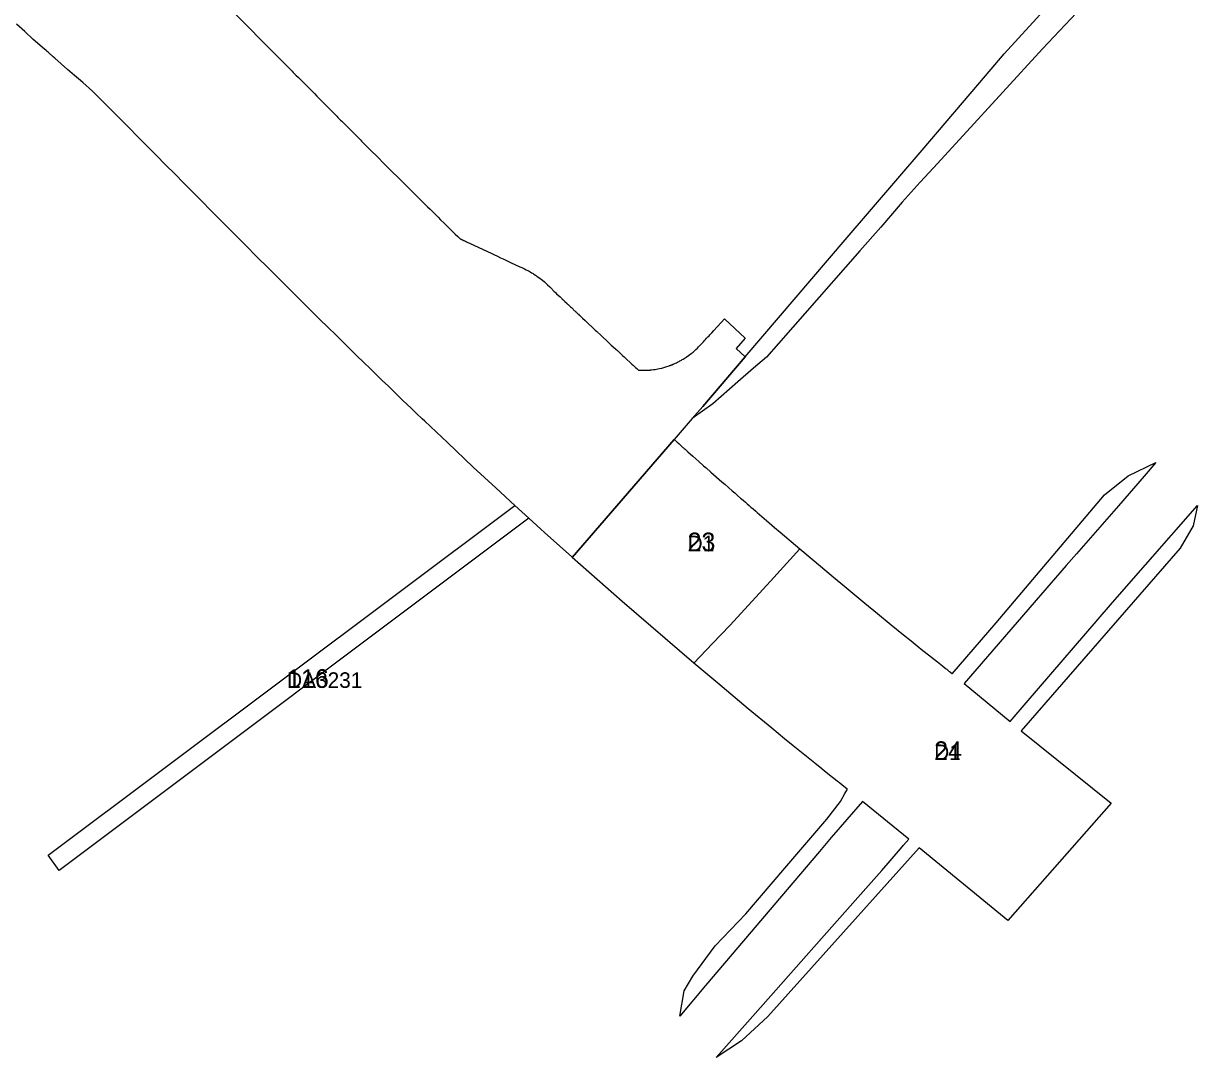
# Model space of a CAD drawing. Extents: x -537012 to -534603, y -1176562 to -1172739.
# Drawn here: x -536079.8 to -535702.9, y -1174980.3 to -1174648.3 of the extents above; entities that cross this region are included whole.
import ezdxf

# ---------------------------------------------------------------- set-up
doc = ezdxf.new("R2010")
doc.units = 0
for name, color, linetype in [('96120023', 7, 'Continuous'), ('96140023', 7, 'Continuous'), ('ID_VPO', 7, 'Continuous'), ('ID_VPS', 7, 'Continuous')]:
    doc.layers.add(name, color=color, linetype=linetype)

msp = doc.modelspace()

# ---------------------------------------------------------------- linework, layer by layer
at = {"layer": '96120023'}
for points in [[(-536047.23, -1174609.35), (-535999.47, -1174657.57), (-535998.21, -1174658.84), (-535997.36, -1174659.7), (-535996.1, -1174660.98), (-535995.25, -1174661.83), (-535994.83, -1174662.25), (-535994.41, -1174662.68), (-535993.56, -1174663.53), (-535993.14, -1174663.96), (-535992.72, -1174664.38), (-535992.3, -1174664.81), (-535991.46, -1174665.66), (-535990.61, -1174666.51), (-535989.77, -1174667.36), (-535988.92, -1174668.21), (-535988.08, -1174669.06), (-535987.24, -1174669.91), (-535986.39, -1174670.77), (-535985.55, -1174671.62), (-535984.71, -1174672.47), (-535983.86, -1174673.32), (-535983.02, -1174674.17), (-535982.6, -1174674.59), (-535982.18, -1174675.01), (-535981.75, -1174675.44), (-535981.33, -1174675.86), (-535980.91, -1174676.29), (-535980.49, -1174676.71), (-535980.07, -1174677.14), (-535979.65, -1174677.56), (-535979.22, -1174677.99), (-535978.8, -1174678.41), (-535978.38, -1174678.83), (-535977.96, -1174679.26), (-535977.54, -1174679.68), (-535977.12, -1174680.11), (-535976.69, -1174680.53), (-535976.27, -1174680.95), (-535975.85, -1174681.38), (-535975.43, -1174681.8), (-535975.01, -1174682.23), (-535974.59, -1174682.65), (-535974.16, -1174683.07), (-535973.74, -1174683.5), (-535973.32, -1174683.92), (-535972.9, -1174684.34), (-535972.48, -1174684.77), (-535972.05, -1174685.19), (-535971.63, -1174685.61), (-535971.21, -1174686.04), (-535970.79, -1174686.46), (-535970.37, -1174686.88), (-535969.95, -1174687.31), (-535968.26, -1174689), (-535966.15, -1174691.11), (-535964.04, -1174693.22), (-535962.35, -1174694.91), (-535961.08, -1174696.17), (-535959.81, -1174697.43), (-535958.54, -1174698.7), (-535957.7, -1174699.54), (-535956.85, -1174700.38), (-535956.43, -1174700.8), (-535955.58, -1174701.64), (-535954.74, -1174702.48), (-535953.89, -1174703.32), (-535953.05, -1174704.16), (-535951.78, -1174705.42), (-535950.93, -1174706.25), (-535950.08, -1174707.09), (-535949.24, -1174707.93), (-535947.97, -1174709.19), (-535946.69, -1174710.44), (-535945.85, -1174711.28), (-535944.57, -1174712.53), (-535943.73, -1174713.36), (-535942.88, -1174714.2), (-535942.03, -1174715.03), (-535941.18, -1174715.87), (-535940.33, -1174716.7), (-535939.63, -1174717.38), (-535939.46, -1174717.47), (-535939.4, -1174717.49), (-535939.36, -1174717.51), (-535939.34, -1174717.52), (-535939.3, -1174717.54), (-535939.26, -1174717.56), (-535939.23, -1174717.57), (-535939.21, -1174717.58), (-535939.19, -1174717.59), (-535939.13, -1174717.62), (-535939.08, -1174717.64), (-535939.04, -1174717.66), (-535939.02, -1174717.67), (-535938.98, -1174717.69), (-535938.96, -1174717.7), (-535938.94, -1174717.71), (-535938.9, -1174717.73), (-535938.87, -1174717.74), (-535938.86, -1174717.75), (-535938.84, -1174717.75), (-535938.83, -1174717.76), (-535938.82, -1174717.76), (-535938.82, -1174717.77), (-535938.81, -1174717.77), (-535938.8, -1174717.77), (-535938.79, -1174717.78), (-535938.78, -1174717.78), (-535938.77, -1174717.79), (-535938.76, -1174717.79), (-535938.75, -1174717.8), (-535938.73, -1174717.81), (-535938.72, -1174717.81), (-535938.71, -1174717.82), (-535938.69, -1174717.82), (-535938.68, -1174717.83), (-535938.66, -1174717.84), (-535938.65, -1174717.84), (-535938.64, -1174717.85), (-535938.62, -1174717.86), (-535938.6, -1174717.87), (-535938.55, -1174717.89), (-535938.54, -1174717.9), (-535938.52, -1174717.9), (-535938.51, -1174717.91), (-535938.5, -1174717.91), (-535938.44, -1174717.94), (-535938.41, -1174717.96), (-535938.37, -1174717.98), (-535938.22, -1174718.04), (-535938.15, -1174718.08), (-535937.86, -1174718.21), (-535937.55, -1174718.36), (-535937.31, -1174718.47), (-535936.55, -1174718.83), (-535933.61, -1174720.2), (-535929.65, -1174722.06), (-535928.75, -1174722.48), (-535927.61, -1174723.01), (-535926.64, -1174723.47), (-535926.16, -1174723.69), (-535925.76, -1174723.88), (-535924.52, -1174724.47), (-535923.38, -1174725), (-535920.41, -1174726.38), (-535919.82, -1174726.66), (-535918.98, -1174727.06), (-535918.39, -1174727.35), (-535917.84, -1174727.62), (-535917.44, -1174727.85), (-535917.08, -1174728.04), (-535916.65, -1174728.29), (-535916.39, -1174728.44), (-535916.15, -1174728.59), (-535915.89, -1174728.76), (-535915.44, -1174729.05), (-535915.14, -1174729.25), (-535914.82, -1174729.47), (-535914.32, -1174729.83), (-535913.2, -1174730.67), (-535912.57, -1174731.22), (-535912.23, -1174731.52), (-535911.54, -1174732.14), (-535910.84, -1174732.83), (-535910.5, -1174733.2), (-535910.11, -1174733.61), (-535909.9, -1174733.82), (-535909.47, -1174734.22), (-535909.04, -1174734.63), (-535908.62, -1174735.04), (-535907.53, -1174736.06), (-535907.07, -1174736.51), (-535906.92, -1174736.65), (-535906.87, -1174736.69), (-535906.82, -1174736.74), (-535906.79, -1174736.77), (-535906.77, -1174736.79), (-535906.75, -1174736.81), (-535906.73, -1174736.82), (-535906.72, -1174736.83), (-535906.71, -1174736.84), (-535906.7, -1174736.85), (-535906.7, -1174736.86), (-535906.69, -1174736.86), (-535906.69, -1174736.87), (-535906.68, -1174736.87), (-535906.68, -1174736.88), (-535906.67, -1174736.88), (-535906.67, -1174736.89), (-535906.66, -1174736.89), (-535906.65, -1174736.9), (-535906.65, -1174736.91), (-535906.64, -1174736.91), (-535906.63, -1174736.92), (-535906.63, -1174736.93), (-535906.62, -1174736.93), (-535906.61, -1174736.94), (-535906.6, -1174736.95), (-535906.42, -1174737.13), (-535906.29, -1174737.24), (-535906.1, -1174737.42), (-535905.96, -1174737.56), (-535905.29, -1174738.19), (-535905.1, -1174738.37), (-535904.94, -1174738.52), (-535904.85, -1174738.61), (-535904.72, -1174738.73), (-535904.63, -1174738.82), (-535904.33, -1174739.1), (-535904.15, -1174739.27), (-535903.9, -1174739.5), (-535903.35, -1174740.03), (-535903.18, -1174740.18), (-535902.97, -1174740.39), (-535902.75, -1174740.59), (-535902.57, -1174740.76), (-535902.29, -1174741.02), (-535902.13, -1174741.17), (-535901.84, -1174741.45), (-535901.63, -1174741.64), (-535901.38, -1174741.88), (-535901.19, -1174742.07), (-535900.31, -1174742.88), (-535899.5, -1174743.65), (-535898.36, -1174744.72), (-535897.3, -1174745.7), (-535896.56, -1174746.4), (-535896.24, -1174746.7), (-535895.88, -1174747.03), (-535895.49, -1174747.41), (-535894.59, -1174748.23), (-535893.82, -1174748.97), (-535892.49, -1174750.2), (-535891.09, -1174751.53), (-535890.47, -1174752.07), (-535889.63, -1174752.86), (-535889.14, -1174753.31), (-535888.7, -1174753.71), (-535888.24, -1174754.13), (-535887.78, -1174754.56), (-535887.44, -1174754.88), (-535886.9, -1174755.36), (-535886.55, -1174755.7), (-535886.22, -1174756.01), (-535885, -1174757.13), (-535884.44, -1174757.64), (-535883.93, -1174758.09), (-535883.3, -1174758.71), (-535882.85, -1174759.1), (-535882.3, -1174759.61), (-535882.25, -1174759.61), (-535882.11, -1174759.62), (-535882.01, -1174759.62), (-535881.93, -1174759.62), (-535881.79, -1174759.63), (-535881.68, -1174759.63), (-535881.49, -1174759.64), (-535881.34, -1174759.64), (-535881.02, -1174759.64), (-535880.58, -1174759.64), (-535880.38, -1174759.64), (-535880.11, -1174759.63), (-535879.91, -1174759.62), (-535879.78, -1174759.62), (-535879.53, -1174759.6), (-535879.33, -1174759.59), (-535878.99, -1174759.57), (-535878.81, -1174759.55), (-535878.61, -1174759.54), (-535878.48, -1174759.52), (-535878.28, -1174759.5), (-535878.13, -1174759.49), (-535877.55, -1174759.42), (-535877.27, -1174759.38), (-535876.96, -1174759.33), (-535876.16, -1174759.19), (-535875.59, -1174759.07), (-535874.91, -1174758.91), (-535874.2, -1174758.72), (-535873.28, -1174758.46), (-535872.49, -1174758.17), (-535872.39, -1174758.14), (-535872.27, -1174758.1), (-535872.16, -1174758.06), (-535872.06, -1174758.02), (-535871.89, -1174757.95), (-535871.73, -1174757.89), (-535871.59, -1174757.83), (-535871.51, -1174757.8), (-535871.43, -1174757.77), (-535871.33, -1174757.73), (-535871.21, -1174757.68), (-535871.09, -1174757.63), (-535870.98, -1174757.58), (-535870.7, -1174757.46), (-535870.44, -1174757.34), (-535870.14, -1174757.2), (-535869.87, -1174757.07), (-535869.63, -1174756.94), (-535869.34, -1174756.8), (-535869.05, -1174756.64), (-535868.79, -1174756.5), (-535868.52, -1174756.34), (-535868.29, -1174756.21), (-535868.01, -1174756.05), (-535867.06, -1174755.45), (-535866.3, -1174754.9), (-535865.46, -1174754.29), (-535864.81, -1174753.76), (-535863.98, -1174753), (-535863.44, -1174752.51), (-535863.04, -1174752.11), (-535862.62, -1174751.67), (-535862.1, -1174751.12), (-535861.51, -1174750.48), (-535861.16, -1174750.1), (-535860.85, -1174749.75), (-535860.47, -1174749.35), (-535860.06, -1174748.91), (-535859.69, -1174748.52), (-535859.4, -1174748.2), (-535858.82, -1174747.58), (-535858.19, -1174746.9), (-535854.7, -1174743.15), (-535848.1, -1174749.3), (-535850.97, -1174752.61), (-535848.15, -1174755.35), (-535861.73, -1174771.25), (-535865.09, -1174775.14), (-535870.89, -1174781.85), (-535894.79, -1174809.5), (-535903.6, -1174819.7), (-535903.75, -1174819.57), (-535912.48, -1174811.71), (-535913.69, -1174810.62), (-535917.53, -1174807.16), (-535922, -1174803.02), (-535928.14, -1174797.34), (-535935.42, -1174790.71), (-535943.68, -1174782.86), (-535950.93, -1174776), (-535951.81, -1174775.17), (-535953.57, -1174773.49), (-535955.32, -1174771.81), (-535957.95, -1174769.29), (-535960.57, -1174766.76), (-535962.75, -1174764.66), (-535964.49, -1174762.97), (-535966.67, -1174760.86), (-535968.41, -1174759.17), (-535970.58, -1174757.06), (-535972.74, -1174754.94), (-535974.9, -1174752.82), (-535977.06, -1174750.7), (-535979.65, -1174748.16), (-535981.81, -1174746.04), (-535984.82, -1174743.06), (-535988.25, -1174739.66), (-535992.11, -1174735.83), (-535995.53, -1174732.43), (-535998.1, -1174729.87), (-536001.08, -1174726.88), (-536004.92, -1174723.05), (-536008.32, -1174719.63), (-536012.14, -1174715.79), (-536016.81, -1174711.1), (-536019.78, -1174708.11), (-536022.32, -1174705.55), (-536025.7, -1174702.13), (-536028.24, -1174699.57), (-536031.2, -1174696.59), (-536034.15, -1174693.6), (-536035, -1174692.75), (-536036.34, -1174691.4), (-536039.83, -1174687.87), (-536040.89, -1174686.79), (-536042.51, -1174685.18), (-536046.52, -1174681.11), (-536049.92, -1174677.67), (-536057.61, -1174669.95), (-536060.7, -1174667.21), (-536062.08, -1174666.04), (-536063.35, -1174664.93), (-536065.6, -1174662.99), (-536067.67, -1174661.17), (-536069.64, -1174659.45), (-536070.2, -1174658.96), (-536070.43, -1174658.76), (-536070.75, -1174658.48), (-536070.95, -1174658.3), (-536071.14, -1174658.14), (-536071.18, -1174658.11), (-536071.24, -1174658.05), (-536071.29, -1174658.01), (-536071.61, -1174657.73), (-536071.85, -1174657.52), (-536072.13, -1174657.28), (-536072.48, -1174656.97), (-536073.68, -1174655.94), (-536075.26, -1174654.55), (-536076.62, -1174653.36), (-536079.3, -1174650.88), (-536082.01, -1174648.5)], [(-535712.62, -1174613.88), (-535752.69, -1174656.44), (-535778.18, -1174684.25), (-535787.66, -1174694.59), (-535791.89, -1174699.19), (-535797.75, -1174705.59), (-535804.55, -1174713.65), (-535811.3, -1174721.31), (-535828.94, -1174741.37), (-535841.26, -1174755.38), (-535845.39, -1174758.98), (-535850.42, -1174763.36), (-535858.47, -1174770.38), (-535865.09, -1174775.14), (-535861.73, -1174771.25), (-535848.15, -1174755.35), (-535816, -1174717.74), (-535791.35, -1174688.89), (-535771.01, -1174665.09), (-535765, -1174658.05), (-535749.98, -1174641.67)]]:
    msp.add_lwpolyline(points, dxfattribs=at)
for points in [[(-535870.89, -1174781.85), (-535869.93, -1174782.74), (-535869.43, -1174783.18), (-535869.01, -1174783.56), (-535868.79, -1174783.76), (-535868.56, -1174783.97), (-535868.33, -1174784.17), (-535868.08, -1174784.39), (-535867.93, -1174784.53), (-535867.69, -1174784.73), (-535867.4, -1174785), (-535867.15, -1174785.21), (-535866.47, -1174785.82), (-535864.95, -1174787.17), (-535863.01, -1174788.9), (-535861.44, -1174790.28), (-535860.64, -1174791), (-535859.14, -1174792.31), (-535855.62, -1174795.41), (-535854.68, -1174796.22), (-535852.26, -1174798.32), (-535851.48, -1174799.01), (-535850.58, -1174799.81), (-535849.6, -1174800.66), (-535848.8, -1174801.34), (-535848.02, -1174802.03), (-535847.52, -1174802.47), (-535846.82, -1174803.06), (-535846.29, -1174803.56), (-535845.54, -1174804.17), (-535844.73, -1174804.89), (-535844.24, -1174805.31), (-535843.47, -1174805.95), (-535842.73, -1174806.61), (-535841.98, -1174807.25), (-535841.26, -1174807.87), (-535838.7, -1174810.13), (-535836.92, -1174811.61), (-535830.57, -1174816.98), (-535840.02, -1174827.31), (-535853.08, -1174841.6), (-535858.57, -1174847.35), (-535864.6, -1174853.66), (-535887.59, -1174833.85), (-535903.6, -1174819.7), (-535894.79, -1174809.5)], [(-535763.09, -1174872.45), (-535757.93, -1174866.46), (-535730.8, -1174834.95), (-535727.94, -1174831.68), (-535702.92, -1174803.1), (-535704.27, -1174809.6), (-535708.49, -1174816.79), (-535759.49, -1174875.44), (-535730.65, -1174898.67), (-535740.9, -1174910.33), (-535763.77, -1174936.3), (-535792.27, -1174912.94), (-535840.8, -1174967.19), (-535849.28, -1174975.01), (-535857.44, -1174980.33), (-535848.23, -1174969.99), (-535842.32, -1174963.3), (-535826.02, -1174944.87), (-535811.96, -1174928.98), (-535804.23, -1174920.24), (-535798.3, -1174913.34), (-535797.25, -1174912.13), (-535795.61, -1174910.22), (-535810.49, -1174898.11), (-535820.47, -1174909.67), (-535824.3, -1174914.18), (-535860.85, -1174957.16), (-535869.09, -1174967.04), (-535867.71, -1174958.89), (-535864.89, -1174954.2), (-535857.7, -1174944.51), (-535847.89, -1174934.15), (-535835.42, -1174919.52), (-535821.9, -1174903.73), (-535817.52, -1174898.06), (-535816.08, -1174895.56), (-535815.76, -1174895.01), (-535815.31, -1174894.19), (-535815.51, -1174894.03), (-535816.96, -1174892.85), (-535817.85, -1174892.16), (-535818.12, -1174891.95), (-535818.47, -1174891.67), (-535819.13, -1174891.14), (-535820.1, -1174890.37), (-535822.62, -1174888.35), (-535823.53, -1174887.61), (-535825.72, -1174885.85), (-535828.91, -1174883.28), (-535832.7, -1174880.19), (-535835.45, -1174877.94), (-535839.59, -1174874.57), (-535847.18, -1174868.32), (-535856.91, -1174860.12), (-535864.6, -1174853.66), (-535858.57, -1174847.35), (-535853.08, -1174841.6), (-535840.02, -1174827.31), (-535830.57, -1174816.98), (-535826.64, -1174820.33), (-535819.89, -1174825.91), (-535816.15, -1174829.08), (-535812.95, -1174831.73), (-535809.67, -1174834.47), (-535805.65, -1174837.7), (-535801.28, -1174841.34), (-535797.31, -1174844.54), (-535794.79, -1174846.56), (-535792.87, -1174848.11), (-535791.04, -1174849.58), (-535789.25, -1174851.01), (-535786.38, -1174853.31), (-535784.8, -1174854.56), (-535783.87, -1174855.31), (-535783.63, -1174855.5), (-535783.42, -1174855.66), (-535782.97, -1174856.02), (-535782.73, -1174856.21), (-535782.58, -1174856.33), (-535782.48, -1174856.41), (-535782.46, -1174856.43), (-535782.43, -1174856.45), (-535782.42, -1174856.46), (-535782.41, -1174856.46), (-535782.4, -1174856.47), (-535782.39, -1174856.48), (-535782.38, -1174856.49), (-535782.36, -1174856.5), (-535782.35, -1174856.51), (-535782.35, -1174856.52), (-535782.34, -1174856.52), (-535782.33, -1174856.53), (-535782.32, -1174856.53), (-535782.32, -1174856.54), (-535782.28, -1174856.57), (-535782.24, -1174856.6), (-535782.17, -1174856.65), (-535782.12, -1174856.69), (-535782.05, -1174856.75), (-535781.92, -1174856.85), (-535781.63, -1174857.08), (-535767.59, -1174840.78), (-535732.8, -1174799.58), (-535725.13, -1174793.48), (-535716.26, -1174789.26), (-535720.01, -1174793.65), (-535728.28, -1174803.12), (-535730.54, -1174805.7), (-535741.81, -1174818.61), (-535745.05, -1174822.31), (-535753.32, -1174831.89), (-535777.81, -1174860.26)]]:
    msp.add_lwpolyline(points, close=True, dxfattribs=at)
at = {"layer": '96140023'}
msp.add_lwpolyline([(-535922, -1174803.02), (-535917.53, -1174807.16), (-536068.27, -1174920.24), (-536071.8, -1174915.38)], close=True, dxfattribs=at)

# ---------------------------------------------------------------- texts
at = {"layer": '96120023'}
for rotation, p in [(360, (-535866.6, -1174817.75)), (0, (-535787.45, -1174884.8))]:
    msp.add_text('D1', height=5, rotation=rotation, dxfattribs=at).set_placement(p)
at = {"layer": '96140023'}
msp.add_text('DA3231', height=5, rotation=360, dxfattribs=at).set_placement((-535995.14, -1174861.63))
at = {"layer": 'ID_VPO'}
msp.add_text('116', height=6, rotation=360, dxfattribs=at).set_placement((-535995.14, -1174861.63))
at = {"layer": 'ID_VPS'}
for s, rotation, p in [('23', 360, (-535866.6, -1174817.75)), ('24', 0, (-535787.45, -1174884.8))]:
    msp.add_text(s, height=6, rotation=rotation, dxfattribs=at).set_placement(p)

doc.saveas('drawing.dxf')
